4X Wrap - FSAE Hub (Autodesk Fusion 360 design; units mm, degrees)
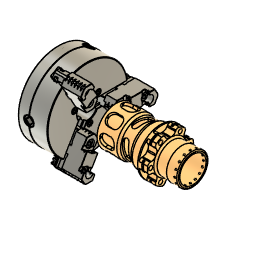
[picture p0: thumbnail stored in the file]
base_feature "Base Feature1" OffsetX 0 OffsetY 0 OffsetZ 0 AngleZ 0 OffsetX 0 OffsetY 0 OffsetZ 0 AngleZ 0
base_feature "Base Feature1"
base_feature "Base Feature1"
base_feature "Base Feature1"
base_feature "Base Feature1"
base_feature "Base Feature1"
base_feature "Base Feature1"
base_feature "Base Feature1"
base_feature "Base Feature1"
base_feature "Base Feature1"
base_feature "Base Feature1"
as_built_joint "As-built1"
as_built_joint "As-built1"
as_built_joint "As-built1"
as_built_joint "As-built2"
as_built_joint "As-built3" OffsetX 0 OffsetY 0 OffsetZ 0 AngleZ 0
step "00000000-0000-0000-0000-000000000000" TotalAngle 360
as_built_joint "As-built4" OffsetX 0 OffsetY 0 OffsetZ 0 AngleZ 0
as_built_joint "As-built9"
joint "Assemble2" alignAngle 90 alignOffsetX 0 alignOffsetY 0 alignOffsetZ 0
as_built_joint "As-built10"
joint "Assemble3" alignAngle 90 alignOffsetX 0 alignOffsetY 0 alignOffsetZ 0
as_built_joint "As-built7" OffsetX 0 OffsetY 0 OffsetZ 0 AngleZ 0
as_built_joint "As-built8" OffsetX 0 OffsetY 0 OffsetZ 0 AngleZ 0
motion_link "MotionLink1" Value1 1 Value2 5.15
position "Position1"
step "00000000-0000-0000-0000-000000000000" TotalAngle 360
as_built_joint "As-built2" OffsetX 0 OffsetY 0 OffsetZ 0 AngleZ 0 DistanceMinimum 2.032
as_built_joint "As-built3" OffsetX 0 OffsetY 0 OffsetZ 0 AngleZ 0 DistanceMaximum -2.032
as_built_joint "As-built4" OffsetX 0 OffsetY 0 OffsetZ 0 AngleZ 0 DistanceMinimum 2.032
motion_link "MotionLink1" Value1 25.4 Value2 25.4
motion_link "MotionLink2" Value1 25.4 Value2 25.4
motion_link "MotionLink3" Value1 1440 Value2 25.4
sketch "Joint Sketch" plane through (14.185, 61.9985, -6.1577) normal (0, 1, 0) x axis (-1, 0, 0)
  circle C1 centre (14.185, 6.1577) radius 39
  circle C2 centre (14.185, 6.1577) radius 27
joint "Assemble2" OffsetX 0 OffsetY 0 OffsetZ 0 AngleZ 0 alignAngle 0 alignOffsetX 0 alignOffsetY 0 alignOffsetZ -177.8
position "Position1"
move_face "MoveFace2"
move_face "MoveFace3"
position "Position2"
delete_face "DeleteFace1"
work_plane "WorkPlane1" AlongDistance -39.243
split_face "SplitFace2"
offset_faces "OffsetFaces3" distance 2.54
chamfer "Chamfer1" distance 2.54
sketch "Sketch2" plane through (0, 0, -149.2391) normal (0, 0, -1) x axis (1, 0, 0)
  line L1 (7.9375, 36.5209) -> (-7.9375, 36.5209)
  line L2 (0, 0.0533) -> (7.9375, 36.5209)
  line L3 (0, 0.0533) -> (-7.9375, 36.5209)
  line L4 (0, -14.8753) -> (-11.0399, 35.8457)
  line L5 (0, -14.8753) -> (11.0399, 35.8457)
  line L6 (0, 14.9819) -> (-4.8351, 37.1962)
  line L7 (0, 14.9819) -> (4.8351, 37.1962)
  circle C1 centre (0, 0) radius 37.3736
  circle C2 centre (0, 0) radius 29.21
  circle C3 centre (0, 0) radius 32.385
  point P4 (-7.9375, 36.5209)
  point P5 (7.9375, 36.5209)
  horizontal L1
  coincident C1 P4
  coincident C1 P5
  concentric C2 C3
  dimension "d40" distance P4 P5 = 15.875
  dimension "d46" distance C2 C3 = 3.175
  dimension "d53" = 3.175
  dimension "d55" = 3.175
extrude "Extrude1" cut sketch "Sketch2" profile of C1 L1 C3 L2 L3 blind -27.94 from offset -6.3754
fillet "Fillet1" radius 9.525
circular_pattern "C-Pattern1" TotalAngle 360
work_plane "WorkPlane2" AlongDistance 1.016
sketch "Sketch3" plane through (0, 0, 1.016) normal (0, 0, 1) x axis (1, 0, 0)
  circle C1 centre (0, 0) radius 50.8
  point P1 (0, 0)
  point P2 (0, 0)
  coincident P1 P2
  dimension "d60" diameter C1 = 101.6
extrude "Extrude2" new body sketch "Sketch3" against normal blind 178.689 bodies "STOCK"
sketch "Sketch5" plane through (0, 0, 0) normal (0, 1, 0) x axis (1, 0, 0)
  line L1 (-29.21, 149.2391) -> (29.21, 149.2391)
  line L2 (29.21, 149.2391) -> (29.21, 112.5361)
  line L3 (-29.21, 149.2391) -> (-29.21, 112.5361)
  line L4 (29.21, 112.5361) -> (31.75, 109.9961)
  line L5 (-31.75, 109.9961) -> (-29.21, 112.5361)
  line L6 (0, 149.2391) -> (0, 78.1191)
  line L7 (29.21, 190.3028) -> (29.21, 149.2391)
  line L8 (0, 190.3028) -> (29.21, 190.3028)
  line L9 (0, 149.2391) -> (0, 190.3028)
  line L10 (31.75, 78.1191) -> (31.75, 109.9961)
  line L11 (31.75, 78.1191) -> (-31.75, 78.1191)
  line L12 (0, 78.1191) -> (31.75, 78.1191)
  point P2 (29.21, 149.2391)
  point P5 (29.21, 149.2391)
  point P3 (-29.21, 149.2391)
  point P7 (-29.21, 149.2391)
  point P10 (0, 149.2391)
  point P13 (31.75, 78.1191)
  point P14 (31.75, 78.1191)
  point P17 (0, 78.1191)
  coincident P2 P5
  coincident P3 P7
  midpoint L1 P10
  perpendicular L1 L7
  perpendicular L2 L8
  perpendicular L1 L9
  coincident P13 P14
  midpoint L11 P17
revolve "Revolve1" sketch "Sketch5" AlongAngle 360
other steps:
create_component "CreateComponent1"
create_component "CreateComponent1"
create_component "CreateComponent2"
create_component "CreateComponent3"
create_component "CreateComponent4"
create_component "CreateComponent5"
create_component "CreateComponent6"
create_component "CreateComponent7"
create_component "CreateComponent2"
create_component "CreateComponent1"
create_component "CreateComponent2"
create_component "CreateComponent3"
create_component "CreateComponent1"
joint_origin "JointOrigin2" OffsetX 0 OffsetY 0 OffsetZ 0 AngleZ 0
joint_origin "JointOrigin2" OffsetX 0 OffsetY 0 OffsetZ 0 AngleZ 0
joint_origin "JointOrigin3" OffsetX 0 OffsetY 0 OffsetZ 0 AngleZ 0
joint_origin "JointOrigin3" OffsetX 0 OffsetY 0 OffsetZ 0 AngleZ 0
joint_origin "JointOrigin1" OffsetX 0 OffsetY 0 OffsetZ 0 AngleZ 0
joint_origin "JointOrigin4" OffsetX 0 OffsetY 0 OffsetZ 0 AngleZ 0
named bodies: "STOCK"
